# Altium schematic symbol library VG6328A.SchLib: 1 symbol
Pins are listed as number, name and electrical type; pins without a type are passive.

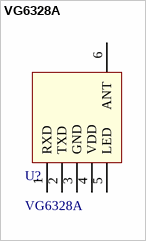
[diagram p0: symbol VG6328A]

## VG6328A
designator U?
footprint SMD_13.5*13MM_6PIN
pins: 1 RXD, 2 TXD, 3 GND, 4 VDD, 5 LED, 6 ANT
